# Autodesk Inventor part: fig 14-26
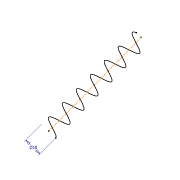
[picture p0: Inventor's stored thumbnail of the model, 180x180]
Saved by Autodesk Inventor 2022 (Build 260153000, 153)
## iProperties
Created: 2007-03
Part Number: fig 14-26
Document SubType Name: Modeling
Designer: Administrator
Density: 1 g/cm^3
Material: Generic
Appearance: Default
Author: Administrator
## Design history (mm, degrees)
node "Sketch1"
sketch "3D Sketch1"
  node "Helical Curve2" dims "d4" = 10, "d5" = 66.31, "d6" = 10, "d7" = 0
